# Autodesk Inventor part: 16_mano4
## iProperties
Created: 2002-11
Part Number: 16_mano4
Material: Par défaut
Document SubType Name: Modélisation
Designer: FIEVET
Control State: 0
Master: False
Checked Out: False
Shininess: 20.0
Length Units: 11269
Angle Units: 11279
Time Units: 11290
Mass Units: 11283
Length Display Precision: 3
Angle Display Precision: 2
Compacted: True
Density: 0.0
Volumn: 0.0
Area: 0.0
PropertySet Name: Model Information
Author: FIEVET
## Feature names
1. Extrusion1
2. Extrusion2
3. Chanfrein1 [Chamfer]
4. Extrusion3
